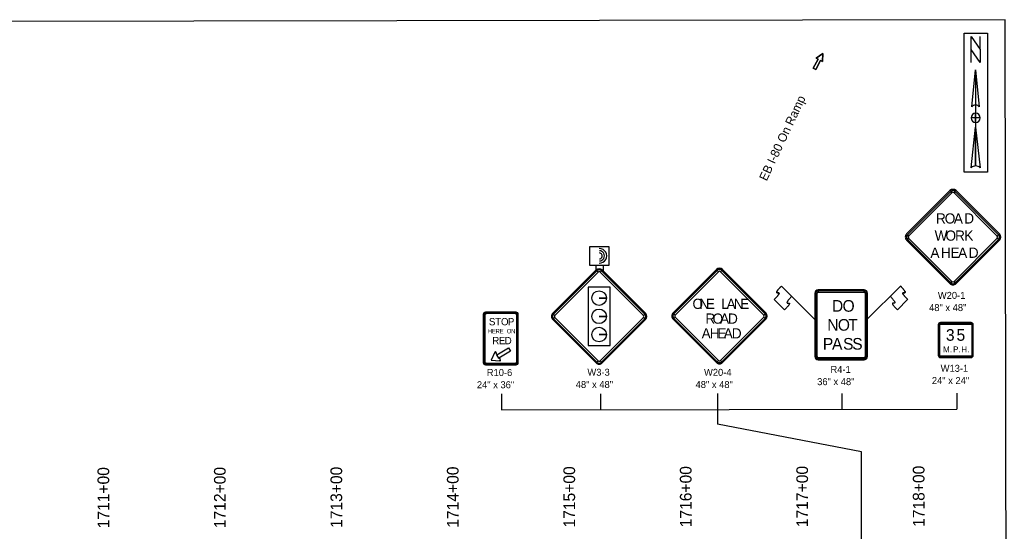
# Model space of a CAD drawing. Extents: x 16513048 to 16518780, y 7009856 to 7010869.
# Drawn here: x 16515769 to 16516617, y 7010430 to 7010869 of the extents above; entities that cross this region are included whole.
import ezdxf

# ---------------------------------------------------------------- set-up
doc = ezdxf.new("R2010")
doc.units = 0
for name, color, linetype in [('Dimensions', 7, 'Continuous'), ('dsnCellElements', 7, 'Continuous'), ('dsnStdLabel', 7, 'Continuous'), ('Level 2', 7, 'Continuous'), ('Level 5', 7, 'Continuous'), ('NamedBoundary', 7, 'Continuous'), ('SheetBorder', 7, 'Continuous'), ('tdCoTitleBlock', 7, 'Continuous')]:
    doc.layers.add(name, color=color, linetype=linetype)

msp = doc.modelspace()

# ---------------------------------------------------------------- linework, layer by layer
at = {"layer": 'dsnCellElements'}
for p, q in [((16516589.5, 7010826.13), (16516592.67, 7010794.45)), ((16516589.5, 7010826.13), (16516589.5, 7010743.75)), ((16516586.33, 7010794.45), (16516586.33, 7010794.45)), ((16516586.46, 7010794.74), (16516587.05, 7010795.4)), ((16516585.54, 7010742.17), (16516589.5, 7010777.02)), ((16516589.5, 7010780.98), (16516589.5, 7010780.98))]:
    msp.add_line(p, q, dxfattribs=at)
for points in [[(16516579.58, 7010857.6), (16516599.69, 7010857.6), (16516599.69, 7010738.48), (16516579.58, 7010738.48)], [(16516593.46, 7010832.47), (16516585.54, 7010843.56), (16516585.54, 7010854.64), (16516593.46, 7010843.56)]]:
    msp.add_lwpolyline(points, close=True, dxfattribs=at)
for points in [[(16516585.54, 7010832.47), (16516585.54, 7010854.64), (16516593.46, 7010843.56), (16516593.46, 7010854.64)], [(16516586.33, 7010794.45), (16516589.5, 7010826.13), (16516589.5, 7010796.03)], [(16516589.5, 7010780.98), (16516589.5, 7010784.94), (16516585.54, 7010784.94)], [(16516593.46, 7010784.94), (16516589.5, 7010784.94), (16516589.5, 7010788.9)], [(16516589.5, 7010743.75), (16516589.5, 7010777.02), (16516593.46, 7010742.17)]]:
    msp.add_lwpolyline(points, dxfattribs=at)
for centre, radius, start, end in [((16516589.5, 7010792.07), 3.96, 90.02039, 143.12574), ((16516589.5, 7010792.07), 3.96, 36.84806, 90.02184), ((16516589.5, 7010784.94), 3.96, 90, 180), ((16516589.5, 7010784.94), 3.96, 180, 270), ((16516589.5, 7010784.94), 3.96, 0, 90), ((16516589.5, 7010784.94), 3.96, 270, 360), ((16516589.5, 7010738.01), 5.74, 89.98939, 133.61895), ((16516589.5, 7010738.01), 5.74, 46.40206, 90.00064)]:
    msp.add_arc(centre, radius, start, end, dxfattribs=at)
at = {"layer": 'dsnStdLabel'}
for p, q in [((16516567.41, 7010722.54), (16516530.24, 7010685.36)), ((16516568.08, 7010721.88), (16516569.18, 7010720.77)), ((16516570.95, 7010720.77), (16516572.06, 7010721.88)), ((16516609.9, 7010685.36), (16516572.72, 7010722.54)), ((16516532.01, 7010683.59), (16516530.9, 7010684.7)), ((16516530.9, 7010680.72), (16516532.01, 7010681.82)), ((16516609.24, 7010684.7), (16516608.13, 7010683.59)), ((16516608.13, 7010681.82), (16516609.24, 7010680.72)), ((16516530.24, 7010680.05), (16516567.41, 7010642.87)), ((16516572.72, 7010642.87), (16516609.9, 7010680.05)), ((16516263.62, 7010654.47), (16516226.44, 7010617.29)), ((16516264.28, 7010653.8), (16516265.39, 7010652.7)), ((16516267.16, 7010652.7), (16516268.26, 7010653.8)), ((16516306.11, 7010617.29), (16516268.93, 7010654.47)), ((16516366.93, 7010654.77), (16516329.75, 7010617.6)), ((16516367.59, 7010654.11), (16516368.7, 7010653)), ((16516370.47, 7010653), (16516371.57, 7010654.11)), ((16516409.42, 7010617.6), (16516372.24, 7010654.77)), ((16516451.53, 7010612), (16516422.82, 7010640.69)), ((16516422.82, 7010640.69), (16516431.68, 7010631.84)), ((16516496.24, 7010612), (16516524.94, 7010640.7)), ((16516524.94, 7010640.7), (16516516.08, 7010631.84)), ((16516569.18, 7010644.65), (16516568.08, 7010643.54)), ((16516572.06, 7010643.54), (16516570.95, 7010644.65)), ((16516272.49, 7010630.32), (16516266.23, 7010630.32)), ((16516266.23, 7010630.32), (16516272.49, 7010630.32)), ((16516451.46, 7010634.6), (16516451.46, 7010580.14)), ((16516452.24, 7010634.6), (16516453.34, 7010634.6)), ((16516493.71, 7010637.41), (16516454.28, 7010637.41)), ((16516454.28, 7010635.54), (16516454.28, 7010636.63)), ((16516493.71, 7010636.63), (16516493.71, 7010635.54)), ((16516494.65, 7010634.6), (16516495.74, 7010634.6)), ((16516496.53, 7010580.14), (16516496.53, 7010634.6)), ((16516425.48, 7010620.32), (16516416.62, 7010629.17)), ((16516522.29, 7010620.33), (16516531.14, 7010629.18)), ((16516166.82, 7010616.38), (16516168.69, 7010616.38)), ((16516167.29, 7010616.38), (16516168.07, 7010616.38)), ((16516168.69, 7010616.38), (16516168.69, 7010618.26)), ((16516168.69, 7010617.01), (16516168.69, 7010617.79)), ((16516194.98, 7010618.26), (16516194.98, 7010616.38)), ((16516194.98, 7010617.79), (16516194.98, 7010617.01)), ((16516194.98, 7010616.38), (16516196.86, 7010616.38)), ((16516195.61, 7010616.38), (16516196.39, 7010616.38)), ((16516228.21, 7010615.52), (16516227.1, 7010616.62)), ((16516227.1, 7010612.64), (16516228.21, 7010613.75)), ((16516272.49, 7010614.67), (16516266.23, 7010614.67)), ((16516266.23, 7010614.67), (16516272.49, 7010614.67)), ((16516305.44, 7010616.62), (16516304.34, 7010615.52)), ((16516304.34, 7010613.75), (16516305.44, 7010612.64)), ((16516331.52, 7010615.82), (16516330.42, 7010616.93)), ((16516330.42, 7010612.95), (16516331.52, 7010614.05)), ((16516408.75, 7010616.93), (16516407.65, 7010615.82)), ((16516407.65, 7010614.05), (16516408.75, 7010612.95)), ((16516226.44, 7010611.98), (16516263.62, 7010574.8)), ((16516268.93, 7010574.8), (16516306.11, 7010611.98)), ((16516329.75, 7010612.28), (16516366.93, 7010575.11)), ((16516372.24, 7010575.11), (16516409.42, 7010612.28)), ((16516557.46, 7010607.46), (16516557.46, 7010581.17)), ((16516557.93, 7010607.46), (16516558.71, 7010607.46)), ((16516585.62, 7010609.34), (16516559.34, 7010609.34)), ((16516559.34, 7010608.09), (16516559.34, 7010608.87)), ((16516585.62, 7010608.87), (16516585.62, 7010608.09)), ((16516586.25, 7010607.46), (16516587.03, 7010607.46)), ((16516587.5, 7010581.17), (16516587.5, 7010607.46)), ((16516272.49, 7010599.02), (16516266.23, 7010599.02)), ((16516266.23, 7010599.02), (16516272.49, 7010599.02)), ((16516176.76, 7010583.84), (16516177.31, 7010583.55)), ((16516177.31, 7010583.55), (16516177.92, 7010583.69)), ((16516453.34, 7010580.14), (16516452.24, 7010580.14)), ((16516454.28, 7010578.11), (16516454.28, 7010579.2)), ((16516493.71, 7010579.2), (16516493.71, 7010578.11)), ((16516495.74, 7010580.14), (16516494.65, 7010580.14)), ((16516558.71, 7010581.17), (16516557.93, 7010581.17)), ((16516559.34, 7010579.77), (16516559.34, 7010580.55)), ((16516559.34, 7010579.3), (16516585.62, 7010579.3)), ((16516585.62, 7010580.55), (16516585.62, 7010579.77)), ((16516587.03, 7010581.17), (16516586.25, 7010581.17)), ((16516168.69, 7010575.07), (16516166.82, 7010575.07)), ((16516168.07, 7010575.07), (16516167.29, 7010575.07)), ((16516168.69, 7010573.19), (16516168.69, 7010575.07)), ((16516168.69, 7010573.66), (16516168.69, 7010574.44)), ((16516181.07, 7010577.04), (16516181.04, 7010576.42)), ((16516181.49, 7010577.51), (16516181.07, 7010577.04)), ((16516196.86, 7010575.07), (16516194.98, 7010575.07)), ((16516194.98, 7010575.07), (16516194.98, 7010573.19)), ((16516194.98, 7010574.44), (16516194.98, 7010573.66)), ((16516196.39, 7010575.07), (16516195.61, 7010575.07)), ((16516265.39, 7010576.57), (16516264.28, 7010575.46)), ((16516268.26, 7010575.46), (16516267.16, 7010576.57)), ((16516368.7, 7010576.88), (16516367.59, 7010575.77)), ((16516371.57, 7010575.77), (16516370.47, 7010576.88)), ((16516454.28, 7010577.33), (16516493.71, 7010577.33))]:
    msp.add_line(p, q, dxfattribs=at)
for points in [[(16516568.08, 7010721.88), (16516530.9, 7010684.7), (16516532.01, 7010683.59), (16516569.18, 7010720.77), (16516568.08, 7010721.88)], [(16516609.24, 7010684.7), (16516572.06, 7010721.88), (16516570.95, 7010720.77), (16516608.13, 7010683.59), (16516609.24, 7010684.7)], [(16516530.9, 7010680.72), (16516568.08, 7010643.54), (16516569.18, 7010644.65), (16516532.01, 7010681.82), (16516530.9, 7010680.72)], [(16516572.06, 7010643.54), (16516609.24, 7010680.72), (16516608.13, 7010681.82), (16516570.95, 7010644.65), (16516572.06, 7010643.54)], [(16516264.28, 7010653.8), (16516227.1, 7010616.62), (16516228.21, 7010615.52), (16516265.39, 7010652.7), (16516264.28, 7010653.8)], [(16516305.44, 7010616.62), (16516268.26, 7010653.8), (16516267.16, 7010652.7), (16516304.34, 7010615.52), (16516305.44, 7010616.62)], [(16516367.59, 7010654.11), (16516330.42, 7010616.93), (16516331.52, 7010615.82), (16516368.7, 7010653), (16516367.59, 7010654.11)], [(16516408.75, 7010616.93), (16516371.57, 7010654.11), (16516370.47, 7010653), (16516407.65, 7010615.82), (16516408.75, 7010616.93)], [(16516275.65, 7010639.64), (16516256.89, 7010639.64), (16516256.89, 7010589.62), (16516275.65, 7010589.62), (16516275.65, 7010639.64)], [(16516452.24, 7010634.6), (16516452.24, 7010580.14), (16516453.34, 7010580.14), (16516453.34, 7010634.6), (16516452.24, 7010634.6)], [(16516493.71, 7010636.63), (16516454.28, 7010636.63), (16516454.28, 7010635.54), (16516493.71, 7010635.54), (16516493.71, 7010636.63)], [(16516495.74, 7010580.14), (16516495.74, 7010634.6), (16516494.65, 7010634.6), (16516494.65, 7010580.14), (16516495.74, 7010580.14)], [(16516168.69, 7010573.19), (16516194.98, 7010573.19), (16516194.98, 7010575.07), (16516196.86, 7010575.07), (16516196.86, 7010616.38), (16516194.98, 7010616.38), (16516194.98, 7010618.26), (16516168.69, 7010618.26), (16516168.69, 7010616.38), (16516166.82, 7010616.38), (16516166.82, 7010575.07), (16516168.69, 7010575.07), (16516168.69, 7010573.19)], [(16516168.07, 7010616.38), (16516168.07, 7010575.07), (16516167.29, 7010575.07), (16516167.29, 7010616.38), (16516168.07, 7010616.38)], [(16516194.98, 7010617.01), (16516168.69, 7010617.01), (16516168.69, 7010617.79), (16516194.98, 7010617.79), (16516194.98, 7010617.01)], [(16516195.61, 7010575.07), (16516195.61, 7010616.38), (16516196.39, 7010616.38), (16516196.39, 7010575.07), (16516195.61, 7010575.07)], [(16516227.1, 7010612.64), (16516264.28, 7010575.46), (16516265.39, 7010576.57), (16516228.21, 7010613.75), (16516227.1, 7010612.64)], [(16516268.26, 7010575.46), (16516305.44, 7010612.64), (16516304.34, 7010613.75), (16516267.16, 7010576.57), (16516268.26, 7010575.46)], [(16516330.42, 7010612.95), (16516367.59, 7010575.77), (16516368.7, 7010576.88), (16516331.52, 7010614.05), (16516330.42, 7010612.95)], [(16516371.57, 7010575.77), (16516408.75, 7010612.95), (16516407.65, 7010614.05), (16516370.47, 7010576.88), (16516371.57, 7010575.77)], [(16516557.93, 7010607.46), (16516557.93, 7010581.17), (16516558.71, 7010581.17), (16516558.71, 7010607.46), (16516557.93, 7010607.46)], [(16516585.62, 7010608.87), (16516559.34, 7010608.87), (16516559.34, 7010608.09), (16516585.62, 7010608.09), (16516585.62, 7010608.87)], [(16516587.03, 7010581.17), (16516587.03, 7010607.46), (16516586.25, 7010607.46), (16516586.25, 7010581.17), (16516587.03, 7010581.17)], [(16516188.53, 7010587.59), (16516190.18, 7010584.74), (16516180.01, 7010578.87), (16516178.37, 7010581.72), (16516188.53, 7010587.59)], [(16516173.5, 7010577.01), (16516181.04, 7010576.42), (16516181.07, 7010577.04), (16516181.49, 7010577.51), (16516180.01, 7010578.87), (16516178.37, 7010581.72), (16516177.92, 7010583.69), (16516177.31, 7010583.55), (16516176.76, 7010583.84), (16516173.5, 7010577.01)], [(16516454.28, 7010578.11), (16516493.71, 7010578.11), (16516493.71, 7010579.2), (16516454.28, 7010579.2), (16516454.28, 7010578.11)], [(16516559.34, 7010579.77), (16516585.62, 7010579.77), (16516585.62, 7010580.55), (16516559.34, 7010580.55), (16516559.34, 7010579.77)], [(16516168.69, 7010574.44), (16516194.98, 7010574.44), (16516194.98, 7010573.66), (16516168.69, 7010573.66), (16516168.69, 7010574.44)]]:
    msp.add_lwpolyline(points, close=True, dxfattribs=at)
for centre in [(16516266.23, 7010630.32), (16516266.23, 7010614.67), (16516266.23, 7010599.02)]:
    msp.add_circle(centre, 6.26, dxfattribs=at)
for centre, radius, start, end in [((16516570.07, 7010719.88), 3.76, 44.99999, 134.99974), ((16516570.07, 7010719.88), 2.82, 44.99999, 134.99974), ((16516570.07, 7010719.88), 1.25, 44.99999, 134.99974), ((16516532.89, 7010682.71), 3.76, 134.99974, 224.99995), ((16516532.89, 7010682.71), 2.82, 134.99974, 224.99995), ((16516532.89, 7010682.71), 1.25, 134.99974, 224.99995), ((16516607.25, 7010682.71), 1.25, 315.00016, 44.9998), ((16516607.25, 7010682.71), 2.82, 315.00016, 44.9998), ((16516607.25, 7010682.71), 3.76, 315.00016, 44.9998), ((16516266.27, 7010651.81), 3.76, 44.99999, 134.99974), ((16516369.58, 7010652.12), 3.76, 44.99999, 134.99974), ((16516266.27, 7010651.81), 2.82, 44.99999, 134.99974), ((16516266.27, 7010651.81), 1.25, 44.99999, 134.99974), ((16516369.58, 7010652.12), 2.82, 44.99999, 134.99974), ((16516369.58, 7010652.12), 1.25, 44.99999, 134.99974), ((16516570.07, 7010645.53), 3.76, 224.99995, 315.00016), ((16516570.07, 7010645.53), 2.82, 224.99995, 315.00016), ((16516570.07, 7010645.53), 1.25, 224.99995, 315.00016), ((16516454.28, 7010634.6), 2.82, 90.00021, 179.99985), ((16516454.28, 7010634.6), 2.03, 90.00021, 179.99985), ((16516454.28, 7010634.6), 0.939, 90.00021, 179.99985), ((16516493.71, 7010634.6), 2.82, 0, 90.00021), ((16516493.71, 7010634.6), 2.03, 0, 90.00021), ((16516493.71, 7010634.6), 0.939, 0, 90.00021), ((16516168.69, 7010616.38), 1.88, 90.00021, 179.99985), ((16516168.69, 7010616.38), 1.41, 90.00021, 179.99985), ((16516168.69, 7010616.38), 0.626, 90.00021, 179.99985), ((16516194.98, 7010616.38), 1.88, 0, 90.00021), ((16516194.98, 7010616.38), 1.41, 0, 90.00021), ((16516194.98, 7010616.38), 0.626, 0, 90.00021), ((16516229.1, 7010614.63), 3.76, 134.99974, 224.99995), ((16516229.1, 7010614.63), 2.82, 134.99974, 224.99995), ((16516229.1, 7010614.63), 1.25, 134.99974, 224.99995), ((16516303.45, 7010614.63), 1.25, 315.00016, 44.9998), ((16516303.45, 7010614.63), 2.82, 315.00016, 44.9998), ((16516303.45, 7010614.63), 3.76, 315.00016, 44.9998), ((16516332.41, 7010614.94), 3.76, 134.99974, 224.99995), ((16516332.41, 7010614.94), 2.82, 134.99974, 224.99995), ((16516332.41, 7010614.94), 1.25, 134.99974, 224.99995), ((16516406.76, 7010614.94), 1.25, 315.00016, 44.9998), ((16516406.76, 7010614.94), 2.82, 315.00016, 44.9998), ((16516406.76, 7010614.94), 3.76, 315.00016, 44.9998), ((16516559.34, 7010607.46), 1.88, 90.00021, 179.99985), ((16516559.34, 7010607.46), 1.41, 90.00021, 179.99985), ((16516559.34, 7010607.46), 0.626, 90.00021, 179.99985), ((16516585.62, 7010607.46), 1.88, 0, 90.00021), ((16516585.62, 7010607.46), 1.41, 0, 90.00021), ((16516585.62, 7010607.46), 0.626, 0, 90.00021), ((16516177.31, 7010583.55), 0.626, 12.62232, 152.27557), ((16516454.28, 7010580.14), 2.82, 179.99985, 270.00006), ((16516454.28, 7010580.14), 2.03, 179.99985, 270.00006), ((16516454.28, 7010580.14), 0.939, 179.99985, 270.00006), ((16516493.71, 7010580.14), 2.82, 270.00006, 0.00027), ((16516493.71, 7010580.14), 2.03, 270.00006, 0.00027), ((16516493.71, 7010580.14), 0.939, 270.00006, 0.00027), ((16516559.34, 7010581.17), 1.88, 179.99985, 270.00006), ((16516559.34, 7010581.17), 1.41, 179.99985, 270.00006), ((16516559.34, 7010581.17), 0.626, 179.99985, 270.00006), ((16516585.62, 7010581.17), 1.88, 270.00006, 0.00027), ((16516585.62, 7010581.17), 1.41, 270.00006, 0.00027), ((16516585.62, 7010581.17), 0.626, 270.00006, 0.00027), ((16516168.69, 7010575.07), 1.88, 179.99985, 270.00006), ((16516168.69, 7010575.07), 1.41, 179.99985, 270.00006), ((16516168.69, 7010575.07), 0.626, 179.99985, 270.00006), ((16516181.07, 7010577.04), 0.626, 267.72427, 47.37758), ((16516194.98, 7010575.07), 1.88, 270.00006, 0.00027), ((16516194.98, 7010575.07), 1.41, 270.00006, 0.00027), ((16516194.98, 7010575.07), 0.626, 270.00006, 0.00027), ((16516266.27, 7010577.46), 3.76, 224.99995, 315.00016), ((16516266.27, 7010577.46), 2.82, 224.99995, 315.00016), ((16516266.27, 7010577.46), 1.25, 224.99995, 315.00016), ((16516369.58, 7010577.76), 3.76, 224.99995, 315.00016), ((16516369.58, 7010577.76), 2.82, 224.99995, 315.00016), ((16516369.58, 7010577.76), 1.25, 224.99995, 315.00016)]:
    msp.add_arc(centre, radius, start, end, dxfattribs=at)
for points in [[(16516416.62, 7010629.17), (16516422.82, 7010635.37), (16516416.62, 7010634.48), (16516422.82, 7010640.69)], [(16516531.14, 7010629.18), (16516524.94, 7010635.38), (16516531.14, 7010634.49), (16516524.94, 7010640.7)], [(16516431.68, 7010631.84), (16516425.48, 7010625.63), (16516431.67, 7010626.52), (16516425.48, 7010620.32)], [(16516516.08, 7010631.84), (16516522.28, 7010625.64), (16516516.09, 7010626.53), (16516522.29, 7010620.33)]]:
    msp.add_open_spline(points, degree=2, dxfattribs=at)
at = {"layer": 'Level 2'}
for p, q in [((16516263.35, 7010658.43), (16516263.35, 7010653.42)), ((16516269.61, 7010658.43), (16516269.61, 7010653.42)), ((16516182.41, 7010548.09), (16516182.43, 7010534.39)), ((16516267.53, 7010548.24), (16516267.56, 7010534.54)), ((16516367.83, 7010548.41), (16516367.87, 7010522.3)), ((16516474.52, 7010548.6), (16516474.54, 7010534.9)), ((16516573.28, 7010548.77), (16516573.3, 7010535.08)), ((16516182.43, 7010534.39), (16516573.3, 7010535.08)), ((16516491.48, 7010498.36), (16516367.87, 7010522.3)), ((16516491.62, 7010416.26), (16516491.48, 7010498.36))]:
    msp.add_line(p, q, dxfattribs=at)
for points in [[(16516452.36, 7010826.49), (16516450.15, 7010827.66), (16516454.25, 7010835.39), (16516452.59, 7010836.27), (16516458.28, 7010840.32), (16516458.12, 7010833.34), (16516456.46, 7010834.22)], [(16516258.34, 7010658.43), (16516258.34, 7010674.7), (16516274.61, 7010674.7), (16516274.61, 7010658.43)]]:
    msp.add_lwpolyline(points, close=True, dxfattribs=at)
for radius in [6.26, 6.26, 4.38, 2.5]:
    msp.add_arc((16516266.48, 7010666.56), radius, 269.40414, 90.54446, dxfattribs=at)
at = {"layer": 'Level 5'}
for p, q in [((16516416.62, 7010629.17), (16516425.48, 7010620.32)), ((16516531.14, 7010629.18), (16516522.29, 7010620.33))]:
    msp.add_line(p, q, dxfattribs=at)
msp.add_lwpolyline([(16516456.46, 7010834.22), (16516458.12, 7010833.34), (16516458.28, 7010840.32), (16516452.59, 7010836.27), (16516454.25, 7010835.39), (16516450.15, 7010827.66), (16516452.36, 7010826.49), (16516456.46, 7010834.22)], dxfattribs=at)
for points in [[(16516422.82, 7010640.69), (16516416.62, 7010634.48), (16516422.82, 7010635.37), (16516416.62, 7010629.17)], [(16516524.94, 7010640.7), (16516531.14, 7010634.49), (16516524.94, 7010635.38), (16516531.14, 7010629.18)], [(16516431.68, 7010631.84), (16516425.48, 7010625.63), (16516431.67, 7010626.52), (16516425.48, 7010620.32)], [(16516516.08, 7010631.84), (16516522.28, 7010625.64), (16516516.09, 7010626.53), (16516522.29, 7010620.33)]]:
    msp.add_open_spline(points, degree=2, dxfattribs=at)
at = {"layer": 'NamedBoundary'}
msp.add_lwpolyline([(16515047.4, 7010866.4), (16515049.16, 7009856.4), (16516616.66, 7009859.13), (16516614.9, 7010869.13)], close=True, dxfattribs=at)

# ---------------------------------------------------------------- texts
at = {"layer": 'Dimensions'}
msp.add_text('EB I-80 On Ramp', height=7.5, rotation=64.81556, dxfattribs=at).set_placement((16516410.08, 7010730.27))
at = {"layer": 'dsnStdLabel'}
for s, height, p in [('R', 8.76, (16516555.47, 7010694.29)), ('O', 8.76, (16516562.98, 7010694.29)), ('A', 8.76, (16516570.77, 7010694.29)), ('D', 8.76, (16516579.72, 7010694.29)), ('W', 8.76, (16516554.32, 7010679.58)), ('O', 8.76, (16516563.63, 7010679.58)), ('R', 8.76, (16516571.85, 7010679.58)), ('K', 8.76, (16516579.79, 7010679.58)), ('A', 8.76, (16516550.68, 7010664.87)), ('H', 8.76, (16516559.8, 7010664.87)), ('E', 8.76, (16516567.92, 7010664.87)), ('A', 8.76, (16516574.46, 7010664.87)), ('D', 8.76, (16516583.57, 7010664.87)), ('O', 8.76, (16516346.41, 7010621.04)), ('N', 8.76, (16516352.3, 7010621.04)), ('E', 8.76, (16516357.93, 7010621.04)), ('L', 8.76, (16516371.07, 7010621.04)), ('A', 8.76, (16516375.67, 7010621.04)), ('N', 8.76, (16516381.82, 7010621.04)), ('E', 8.76, (16516387.44, 7010621.04)), ('W20-1', 6, (16516557.09, 7010629.67)), ('D', 10.01, (16516466.17, 7010618.64)), ('O', 10.01, (16516475.24, 7010618.64)), ('48" x 48"', 6, (16516549.55, 7010619.17)), ('S', 6.26, (16516171.6, 7010606.99)), ('T', 6.26, (16516176.99, 7010606.99)), ('O', 6.26, (16516181.99, 7010606.99)), ('P', 6.26, (16516187.87, 7010606.99)), ('R', 8.76, (16516357.48, 7010608.37)), ('O', 8.76, (16516363.63, 7010608.37)), ('A', 8.76, (16516370.06, 7010608.37)), ('D', 8.76, (16516376.9, 7010608.37)), ('A', 8.76, (16516354.25, 7010595.69)), ('H', 8.76, (16516361.2, 7010595.69)), ('E', 8.76, (16516367.81, 7010595.69)), ('A', 8.76, (16516373.18, 7010595.69)), ('D', 8.76, (16516380.12, 7010595.69)), ('N', 10.01, (16516462.1, 7010602.36)), ('O', 10.01, (16516471.18, 7010602.36)), ('T', 10.01, (16516480.1, 7010602.36)), ('H', 3.76, (16516170.56, 7010600.11)), ('E', 3.76, (16516174.14, 7010600.11)), ('R', 6.26, (16516174.48, 7010590.72)), ('R', 3.76, (16516177.27, 7010600.11)), ('E', 6.26, (16516180.16, 7010590.72)), ('E', 3.76, (16516180.85, 7010600.11)), ('D', 6.26, (16516185.14, 7010590.72)), ('O', 3.76, (16516186.9, 7010600.11)), ('N', 3.76, (16516190.59, 7010600.11)), ('P', 10.01, (16516458.34, 7010586.09)), ('A', 10.01, (16516466.19, 7010586.09)), ('S', 10.01, (16516475.69, 7010586.09)), ('S', 10.01, (16516483.55, 7010586.09)), ('3', 10.01, (16516564.02, 7010593.7)), ('5', 10.01, (16516573.1, 7010593.7)), ('M', 5.01, (16516561.58, 7010583.83)), ('P', 5.01, (16516570.22, 7010583.83)), ('H', 5.01, (16516577.29, 7010583.83)), ('.', 5.01, (16516567.48, 7010583.83)), ('.', 5.01, (16516574.55, 7010583.83)), ('.', 5.01, (16516582.53, 7010583.83)), ('R4-1', 6, (16516464.89, 7010566.14)), ('W13-1', 6, (16516559.49, 7010567.08)), ('R10-6', 6, (16516169.81, 7010563.49)), ('W3-3', 6, (16516256.19, 7010563.72)), ('W20-4', 6, (16516356.3, 7010563.64)), ('24" x 24"', 6, (16516551.94, 7010556.58)), ('24" x 36"', 6, (16516161.3, 7010552.99)), ('48" x 48"', 6, (16516246.18, 7010553.22)), ('48" x 48"', 6, (16516349.04, 7010553.14)), ('36" x 48"', 6, (16516453.46, 7010555.64))]:
    msp.add_text(s, height=height, dxfattribs=at).set_placement(p)
at = {"layer": 'SheetBorder'}
for s, p in [('1715+00', (16516245.67, 7010433.48)), ('1716+00', (16516345.67, 7010433.66)), ('1717+00', (16516445.67, 7010433.83)), ('1718+00', (16516545.67, 7010434.01)), ('1711+00', (16515845.67, 7010432.79)), ('1712+00', (16515945.67, 7010432.96)), ('1713+00', (16516045.67, 7010433.13)), ('1714+00', (16516145.67, 7010433.31))]:
    msp.add_text(s, height=10.02, rotation=90.09989, dxfattribs=at).set_placement(p)
at = {"layer": 'tdCoTitleBlock'}
msp.add_text('1715+00', height=10.02, rotation=90.09989, dxfattribs=at).set_placement((16516245.67, 7010433.48))

doc.saveas('drawing.dxf')
